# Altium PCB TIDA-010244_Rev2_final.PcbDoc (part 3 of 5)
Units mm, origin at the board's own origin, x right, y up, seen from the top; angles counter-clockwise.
Board outline 155.23 x 187.6 mm, 4 copper layers (GND/Signal 1, Solid GND Layer 1, Solid Power Layer 1, GND/Signal Layer 2), stack 1.59 mm thick; 350 components, 237 nets, 1153 pads, 380 vias.
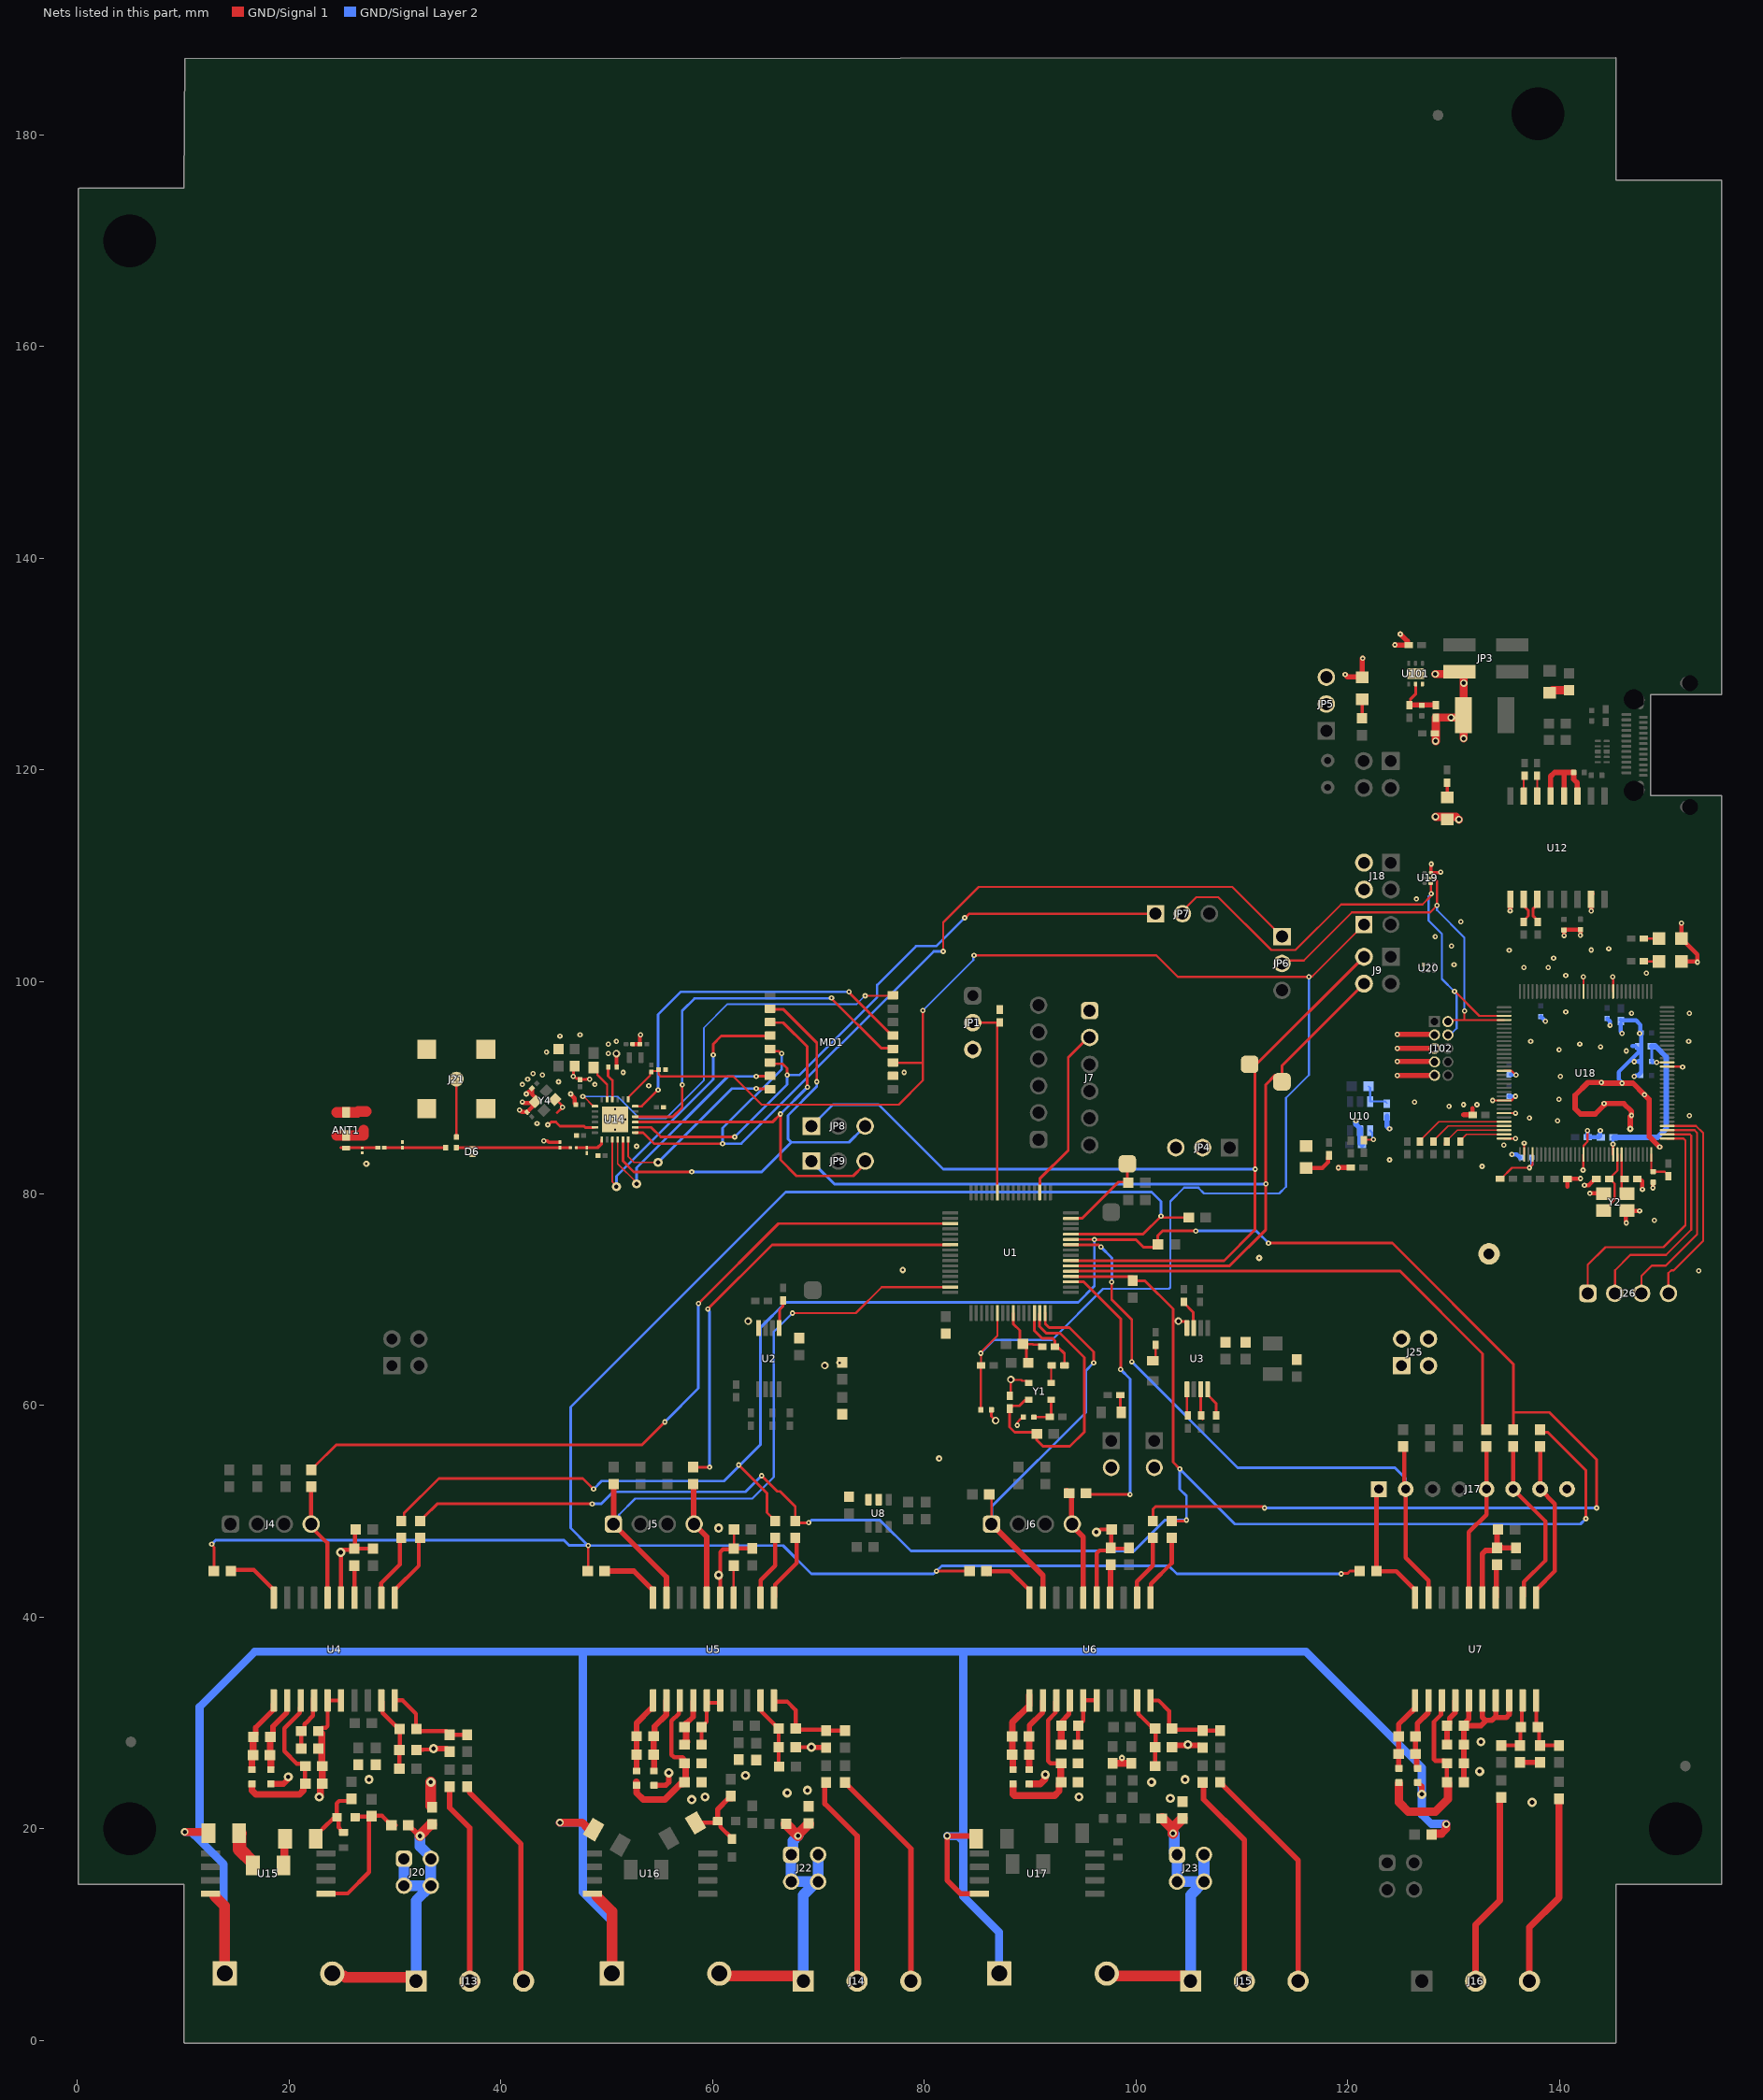
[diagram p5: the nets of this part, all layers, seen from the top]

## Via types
v1: diameter 0.5, hole 0.2, GND/Signal 1 to GND/Signal Layer 2, tented both sides, 236 vias
v2: diameter 0.5, hole 0.2, GND/Signal 1 to GND/Signal Layer 2, 46 vias
v3: diameter 0.864, hole 0.406, GND/Signal 1 to GND/Signal Layer 2, 41 vias
v4: diameter 0.7, hole 0.4, GND/Signal 1 to GND/Signal Layer 2, tented both sides, 40 vias
v5: diameter 0.61, hole 0.203, GND/Signal 1 to GND/Signal Layer 2, tented both sides, 10 vias
v6: diameter 0.4, hole 0.2, GND/Signal 1 to GND/Signal Layer 2, tented both sides, 7 vias

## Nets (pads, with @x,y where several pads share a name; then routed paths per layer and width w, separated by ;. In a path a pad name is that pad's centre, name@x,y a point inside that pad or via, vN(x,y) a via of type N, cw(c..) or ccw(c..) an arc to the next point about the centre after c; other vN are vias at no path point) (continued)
ADC_CS2: J5.1 R39.1 U1.31 U5.19 | length 62.1
  GND/Signal 1 w0.2: v1(67.564,68.707) 73.533,68.707 75.983,71.157 U1.31@82.466,71.157
  GND/Signal 1 w0.508: J5.1@50.648,48.768 50.66,48.781 50.66,52.565 R39.1@50.673,52.578 ; J5.1@50.927,48.768 50.927,48.489 55.651,43.764 U5.19@55.651,41.807
  GND/Signal Layer 2 w0.2: J5.1@50.648,48.768 51.18,49.3 51.18,49.656 52.705,51.181 63.754,51.181 65.786,53.213 65.786,66.929 v1(67.564,68.707)
ADC_CS3: J6.1 R42.1 U1.47 U6.19 | length 38.7
  GND/Signal 1 w0.254: R42.1@86.144,51.562 86.36,51.346 86.36,49.022 J6.1@86.233,48.895 ; U1.47@91.416,68.707 91.439,68.684 91.439,67.692 91.798,67.333 93.703,67.333 96.012,65.024 v1(96.012,64.008)
  GND/Signal 1 w0.508: J6.1@86.36,48.768 91.211,43.917 U6.19@91.211,41.807
  GND/Signal Layer 2 w0.254: J6.1@86.36,48.768 86.401,48.809 86.401,50.46 95.25,59.309 95.25,63.246 v1(96.012,64.008)
ADC_CS4: J17.2 R99.1 U1.58 U7.19 | length 62.4
  GND/Signal 1 w0.254: U1.58@93.266,75.157 U1.58@93.866,75.157 96.475,75.157 v1@96.73,74.902 ; v1(97.706,71.633) 97.706,69.987 99.605,68.089 v1@99.605,64.127
  GND/Signal 1 w0.381: R99.1@125.349,56.134 125.349,52.197 J17.2@125.476,52.07 125.476,45.593 127.635,43.434 U7.19@127.635,41.807
  GND/Signal Layer 2 w0.254: v1(96.687,74.945) 97.728,73.904 v1@97.728,71.613 ; v1@99.599,64.104 109.601,54.102 124.46,54.102 125.476,53.086 J17.2@125.476,52.07
  other v1: 99.595,64.101
ADC_DIN_MSP_DOUT: R29.2 R31.1 R37.2 R45.2 R90.2 U1.60 | length 210.2
  GND/Signal 1 w0.254: v1(12.7,46.863) 12.7,46.796 12.916,46.58 R29.2@12.916,44.323 ; R37.2@48.222,44.323 48.26,44.361 v1(48.26,46.736) ; v1(81.153,44.323) R45.2@84.29,44.323 ; U1.60@93.866,76.157 100.668,76.157 v1(102.362,77.851) 102.429,77.851 102.556,77.724 R31.1@104.991,77.724 ; v1(119.38,44.069) 119.427,44.116 120.002,44.116 120.209,44.323 R90.2@121.12,44.323
  GND/Signal Layer 2 w0.254: v1(12.7,46.863) 13.081,47.244 45.974,47.244 46.448,46.77 v1@48.226,46.77 ; v1(48.26,46.736) v1@48.226,46.77 ; v1@48.387,46.736 66.675,46.736 69.342,44.069 80.881,44.069 81.135,44.323 v1(81.153,44.323) 81.661,44.831 103.091,44.831 103.853,44.069 v1(119.38,44.069) ; v1(102.362,77.851) 102.362,79.248 101.473,80.137 66.929,80.137 46.609,59.817 46.609,48.387 v1@48.226,46.77
ADC_DIN_MSP_DOUT_H: J17.1 R90.1 U7.20 | length 12.9
  GND/Signal 1 w0.406: J17.1@122.682,52.07 122.72,52.032 R90.1@122.72,44.323 124.599,44.323 126.365,42.557 U7.20@126.365,41.807
ADC_DOUT_MSP_DIN: R25.1 R30.2 R38.2 R46.2 R91.2 U1.59 | length 205.4
  GND/Signal 1 w0.254: R30.2@30.607,49.06 30.869,49.322 30.869,49.792 34.163,53.086 47.752,53.086 v1(48.768,52.07) ; v1(62.484,54.356) 65.151,51.689 65.151,49.847 65.913,49.085 R38.2@65.913,49.06 ; U1.59@93.866,75.657 93.875,75.648 96.07,75.648 v1(96.079,75.64) 100.001,75.64 100.711,74.93 101.727,74.93 R25.1@101.854,75.057 ; R46.2@101.6,49.06 101.854,49.314 101.719,49.314 101.6,49.433 101.6,50.165 101.854,50.419 111.947,50.419 112.074,50.292 v1(112.141,50.292) ; R25.1@102.07,75.184 102.07,76.035 102.489,76.454 v1(105.664,76.454) ; v1(112.522,75.311) 124.206,75.311 135.636,63.881 135.636,59.32 ; R91.2@135.636,57.696 135.636,59.32 ; v1(143.51,50.292) 143.51,54.864 139.054,59.32 135.636,59.32
  GND/Signal Layer 2 w0.254: v1(48.768,52.07) 49.53,52.832 61.087,52.832 62.547,54.292 64.516,56.261 64.516,67.31 66.929,69.723 68.834,69.723 94.539,69.723 96.079,71.262 v1(96.079,75.64) ; v1(105.664,76.454) 111.379,76.454 v1(112.522,75.311) ; v1(112.141,50.292) v1(143.51,50.292)
ADC_DOUT_MSP_DIN_H: J17.6 R91.1 U7.12 | length 16.3
  GND/Signal 1 w0.381: J17.6@135.636,52.07 138.684,49.022 138.684,45.339 136.634,43.289 136.634,41.916 U7.12@136.525,41.807 ; J17.6@135.636,52.197 R91.1@135.636,56.096
ADC_DRDY_1: R26.2 U1.19 | length 74.7
  GND/Signal 1 w0.254: R26.2@22.098,53.886 22.098,53.911 22.446,54.259 22.471,54.259 24.473,56.261 53.34,56.261 v1(55.499,58.42) ; v1(58.674,69.596) 66.235,77.157 U1.19@82.466,77.157
  GND/Signal Layer 2 w0.254: v1(55.499,58.42) 58.674,61.595 v1(58.674,69.596)
ADC_DRDY_1_H: J4.4 R26.1 U4.16 | length 11.5
  GND/Signal 1 w0.381: J4.4@22.098,48.768 22.098,51.976 22.192,52.07 R26.1@22.352,52.07 ; J4.4@22.606,48.514 22.386,48.294 22.386,48.226 23.622,46.99 U4.16@23.622,41.148
ADC_DRDY_2: R33.2 U1.23 | length 42.1
  GND/Signal 1 w0.254: R33.2@58.166,54.14 v1(59.728,54.14) v1@59.817,54.229 ; v1(59.563,69.088) 65.632,75.157 U1.23@82.466,75.157
  GND/Signal Layer 2 w0.254: v1@59.563,69.021 59.728,68.856 v1(59.728,54.14)
ADC_DRDY_2_H: J5.4 R33.1 U5.16 | length 11.3
  GND/Signal 1 w0.508: R33.1@58.166,52.578 58.217,52.527 58.217,48.819 J5.4@58.268,48.768 ; J5.4@58.293,48.743 59.461,47.574 U5.16@59.461,41.807
ADC_DRDY_3: R41.2 U1.51 | length 27.2
  GND/Signal 1 w0.254: U1.51@93.866,71.657 95.055,71.657 98.552,68.16 v1@98.552,63.396 ; R41.2@95.377,51.816 95.631,51.562 v1(99.441,51.562)
  GND/Signal Layer 2 w0.254: v1(98.552,63.373) 99.441,62.484 v1(99.441,51.562)
ADC_DRDY_3_H: J6.4 R41.1 U6.16 | length 10.4
  GND/Signal 1 w0.508: R41.1@93.453,51.924 R41.1@93.472,51.943 ; J6.4@93.599,48.895 93.916,49.212 R41.1@93.916,51.816 ; J6.4@93.899,48.687 95.021,47.565 U6.16@95.021,41.807
ADC_DRDY_4: R87.2 U1.53 | length 49.4
  GND/Signal 1 w0.254: U1.53@93.866,72.657 124.955,72.657 132.748,64.864 132.748,58.069 133.032,57.785 R87.2@133.096,57.785
ADC_DRDY_4_H: J17.5 R87.1 U7.16 | length 14.7
  GND/Signal 1 w0.406: U7.16@131.445,41.807 131.445,48.006 133.096,49.657 133.096,51.689 J17.5@132.969,51.816 ; R87.1@132.969,56.007 133.096,55.88 J17.5@133.096,52.07
ADC_from_Buf_1: R18.1 U3.3 | length 2.8
  GND/Signal 1 w0.254: R18.1@104.521,69.758 104.521,69.658 105.41,68.769 U3.3@105.41,67.289
ADC_from_Buf_2: R21.1 U3.5 | length 3
  GND/Signal 1 w0.254: U3.5@104.859,60.964 104.859,61.446 U3.5@104.816,61.489 104.816,59.106 R21.1@104.902,59.02
ADC_from_Buf_3: R22.1 U3.7 | length 2.9
  GND/Signal 1 w0.254: U3.7@106.116,61.489 106.116,58.857 R22.1@106.299,58.674
ADC_from_Buf_4: R20.1 U3.8 | length 2.8
  GND/Signal 1 w0.254: U3.8@106.766,61.489 106.766,60.964 107.569,60.161 R20.1@107.569,59.055
ADC_SYNC_RESET: R24.1 R27.2 R34.2 R43.2 R88.2 U1.52 | length 163.3
  GND/Signal 1 w0.254: R27.2@32.385,49.06 32.385,49.085 32.733,49.433 32.758,49.433 33.998,50.673 v1(48.641,50.673) ; v1(64.643,53.34) 66.127,51.856 66.381,51.856 67.818,50.419 R34.2@67.818,49.06 67.983,48.895 v1(69.088,48.895) ; U1.52@93.866,72.157 R24.1@99.695,72.157 ; R24.1@99.695,71.755 100.838,71.755 103.505,69.088 103.505,54.61 v1(104.14,53.975) ; R43.2@103.378,49.06 104.619,49.06 104.708,49.149 v1(104.775,49.149) ; R88.2@138.176,57.696 138.413,57.459 138.883,57.459 142.494,53.848 v1(142.494,49.276)
  GND/Signal Layer 2 w0.254: v1(48.641,50.673) 49.476,50.673 50.619,51.816 63.119,51.816 v1(64.643,53.34) ; v1(69.088,48.895) 69.106,48.895 69.36,49.149 75.819,49.149 78.74,46.228 99.822,46.228 102.743,49.149 v1(104.775,49.149) ; v1@104.902,49.149 v1(104.775,49.149) ; v1(142.494,49.276) 141.986,48.768 109.347,48.768 v1(104.14,53.975) 104.14,52.07 104.775,51.435 v1(104.775,49.149)
ADC_SYNC_RESET_H: J17.7 R88.1 U7.11 | length 14.5
  GND/Signal 1 w0.406: U7.11@137.795,42.557 139.573,44.335 139.573,50.673 J17.7@138.176,52.07 ; J17.7@138.176,52.451 R88.1@138.176,56.096
Antenna: C114.1 L4.1 U14.1 | length 3.1
  GND/Signal 1 w0.25: U14.1@49.55,84.92 U14.1@49.55,85.095
  GND/Signal 1 w0.297: L4.1@47.117,84.328 L4.1@47.138,84.328 C114.1@48.006,84.328 ; C114.1@48.023,84.328 49.149,84.328 49.526,84.705 49.526,84.92 U14.1@49.526,85.071
BSL_Invoke: JP1.2 R10.2 U1.11 | length 18.4
  GND/Signal 1 w0.254: JP1.2@84.455,96.139 86.811,96.139 R10.2@86.868,96.082 ; R10.2@86.893,96.082 86.893,80.13 U1.11@86.916,80.107
CC_RESET: C5.2 C116.2 J2.1 MD1.11 R3.1 R122.2 U1.38 U14.13 | length 159.3
  GND/Signal 1 w0.2: U14.13@52.05,88.895 52.05,89.07 54.119,91.139 R122.2@54.119,91.457 ; R122.2@54.229,91.491 54.305,91.567 C116.2@54.864,91.567 ; C116.2@54.915,91.694 54.915,91.262 55.118,91.059 61.976,91.059 64.643,88.392 77.597,88.392 79.883,90.678 79.883,92.329 ; MD1.11@76.962,92.329 79.883,92.329 ; v1(79.883,97.282) 79.883,92.329 ; v1(84.709,102.489) 101.917,102.489 103.95,100.457 v1(116.332,100.457) 116.389,100.514 116.643,100.514 J2.1@121.539,105.41 ; C5.2@85.471,59.563 85.352,59.682 85.352,63.727 R3.1@85.379,63.754 85.379,65.024 85.39,65.024 85.487,65.121 85.487,65.132 86.916,66.561 U1.38@86.916,68.707
  GND/Signal Layer 2 w0.2: v1(79.883,97.282) 84.652,102.051 84.652,102.432 v1(84.709,102.489) ; v1(85.344,64.897) 86.614,66.167 92.075,66.167 96.901,70.993 103.124,70.993 103.251,71.12 103.251,79.248 104.552,80.549 105.918,80.549 ; 105.918,80.518 106.426,80.01 113.538,80.01 114.173,80.645 114.173,89.027 116.332,91.186 v1(116.332,100.457) v1@116.332,100.584
CC_SWDCK: JP7.1 MD1.6 U14.8 | length 62
  GND/Signal 1 w0.24: U14.8@52.7,86.245 54.217,86.245 55.118,85.344 v1(62.103,85.344) ; MD1.6@65.405,92.456 65.609,92.252 66.624,92.252 67.056,91.82 v1(67.056,91.186) ; v1(83.82,106.045) 83.89,106.045 84.271,106.426 JP7.1@101.854,106.426
  GND/Signal Layer 2 w0.24: v1(62.103,85.344) 67.056,90.297 v1(67.056,91.186) 68.214,91.186 75.554,98.526 75.554,99.684 79.234,103.364 81.139,103.364 v1(83.82,106.045)
CC_SWDIO: JP6.1 MD1.5 U14.7 | length 87
  GND/Signal 1 w0.2: v1@81.661,102.87 81.788,102.997 81.788,105.6 85.154,108.966 109.093,108.966 JP6.1@113.792,104.267
  GND/Signal 1 w0.24: U14.7@52.7,85.745 52.705,85.74 53.452,85.74 54.483,84.709 v1(60.96,84.709) ; MD1.5@65.381,93.623 MD1.5@65.405,93.599 ; MD1.5@65.659,93.536 65.759,93.436 66.277,93.436 66.495,93.218 v1(66.548,93.218)
  GND/Signal Layer 2 w0.24: v1(66.548,93.218) 66.548,91.757 60.96,86.169 v1(60.96,84.709) 62.738,84.709 80.899,102.87 v1(81.788,102.87)
CTS_FTDI: J7.2 U1.3 | length 16.8
  GND/Signal 1 w0.254: U1.3@90.916,80.107 90.916,81.391 93.599,84.074 93.599,92.837 95.441,94.679 J7.2@95.821,94.679
DCDC_HGND_A: C18.1 C19.2 FB1.1 U4.2 | length 7
  GND/Signal 1 w0.508: C19.2@18.288,28.448 18.478,28.638 18.478,29.654 19.791,30.967 19.791,32.061 U4.2@19.837,32.107
  GND/Signal 1 w0.635: C19.2@18.232,28.448 18.232,26.972 C18.1@18.206,26.946 18.288,26.864 FB1.1@18.288,25.821
DCDC_HGND_B: C27.1 C28.2 FB3.1 U5.2 | length 7
  GND/Signal 1 w0.559: C27.1@54.431,26.978 54.431,28.777 54.547,28.893 54.547,29.655 55.631,30.739 55.631,32.087 U5.2@55.651,32.107 ; FB3.1@54.503,25.754 C27.1@54.503,27.071
DCDC_HGND_C: C38.1 C39.2 FB5.1 U6.2 | length 6.7
  GND/Signal 1 w0.508: C39.2@89.938,28.727 89.938,29.74 91.165,30.967 91.165,32.061 U6.2@91.211,32.107
  GND/Signal 1 w0.635: C39.2@89.903,28.702 89.909,28.696 89.909,27.058 C38.1@89.916,27.051 ; C38.1@89.914,26.885 89.914,25.783 FB5.1@89.916,25.781
DCDC_HGND_D: C69.1 C70.2 FB7.1 U7.2 | length 7.1
  GND/Signal 1 w0.508: C69.1@126.403,27.178 C70.2@126.403,28.702 ; C69.1@126.492,27.178 126.523,27.147 126.523,25.765 126.594,25.694 FB7.1@126.619,25.694 ; C70.2@126.586,28.702 126.586,29.939 127.589,30.942 127.589,32.212 U7.2@127.635,32.258
DCDC_OUT_A: C18.2 C19.1 FB2.1 U4.1 | length 6.7
  GND/Signal 1 w0.508: C19.1@16.632,28.663 16.846,28.876 16.846,29.546 18.521,31.221 18.521,31.729 U4.1@18.542,31.75
  GND/Signal 1 w0.635: FB2.1@16.51,25.821 16.51,26.85 C18.2@16.606,26.946 ; C18.2@16.619,27.033 16.619,28.65 C19.1@16.632,28.663
DCDC_OUT_B: C27.2 C28.1 FB4.1 U5.1 | length 7.5
  GND/Signal 1 w0.559: FB4.1@52.832,25.44 52.832,26.924 C27.2@52.959,27.051 ; C27.2@52.832,26.978 52.832,29.972 54.196,31.336 54.361,31.336 54.381,31.357 U5.1@54.381,32.107
DCDC_OUT_C: C38.2 C39.1 FB6.1 U6.1 | length 7.6
  GND/Signal 1 w0.635: C38.2@88.314,27.051 88.314,28.605 88.314,30.021 89.916,31.623 U6.1@89.916,32.639 ; C38.2@88.392,27.051 88.361,27.02 88.361,25.752 88.369,25.745 FB6.1@88.394,25.745
DCDC_OUT_D: C69.2 C70.1 FB8.1 U7.1 | length 6.8
  GND/Signal 1 w0.508: C70.1@124.803,28.702 124.803,25.946 FB8.1@124.841,25.908 ; C70.1@124.803,28.791 124.803,29.845 126.365,31.369 U7.1@126.365,32.107
DEBUG_ID4: R113.1 U18.63 | length 4.5
  GND/Signal 1 w0.16: R113.1@130.556,84.963 130.604,84.963 131.226,85.584 U18.63@134.769,85.584
DEBUG_ID5: R114.1 U18.62 | length 6.3
  GND/Signal 1 w0.16: R114.1@129.159,84.582 129.159,84.788 130.356,85.984 U18.62@134.769,85.984
DEBUG_ID6: R115.1 U18.61 | length 7.3
  GND/Signal 1 w0.16: R115.1@128.016,84.963 128.064,84.963 129.486,86.384 U18.61@134.769,86.384
DEBUG_ID7: R116.1 U18.60 | length 8.6
  GND/Signal 1 w0.16: R116.1@126.873,85.09 126.921,85.09 128.616,86.784 U18.60@134.769,86.784
DIO6_SCL: MD1.16 U14.19 | length 39.4
  GND/Signal 1 w0.16: v1(47.752,89.154) 47.817,89.089 47.931,89.089 48.68,88.34 48.68,88.29 48.725,88.245 U14.19@48.9,88.245 ; v1(74.422,98.679) MD1.16@77.089,98.679
  GND/Signal Layer 2 w0.16: v1(47.752,89.154) 51.054,89.154 53.086,87.122 55.626,87.122 59.182,90.678 59.182,95.631 61.435,97.884 73.627,97.884 v1(74.422,98.679)
DIO8_SDA: MD1.4 U14.3 | length 27.5
  GND/Signal 1 w0.16: U14.3@50.55,85.095 50.55,81.086 50.927,80.709 v3(50.927,80.645)
  GND/Signal 1 w0.25: v1(60.071,93.091) 60.071,94.107 60.833,94.869 MD1.4@65.405,94.869
  GND/Signal Layer 2 w0.25: v3(50.927,80.645) 50.927,81.639 53.622,84.334 60.071,90.783 v1(60.071,93.091)
DIO11: MD1.7 U14.4 | length 22.8
  GND/Signal 1 w0.16: U14.4@51.05,85.095 51.05,82.808 52.832,81.026 v3(52.832,80.899)
  GND/Signal 1 w0.25: v1(64.135,91.059) 64.16,91.084 65.43,91.084 MD1.7@65.532,91.186
  GND/Signal Layer 2 w0.25: v3(52.832,80.899) 52.832,82.423 61.468,91.059 v1(64.135,91.059)
DIO13_PICO: MD1.8 U14.6 | length 18.2
  GND/Signal 1 w0.16: U14.6@52.05,85.095 52.05,83.459 52.578,82.931 v3(54.864,82.931)
  GND/Signal 1 w0.25: v1(64.135,89.916) 64.174,89.877 65.317,89.877 MD1.8@65.405,89.789
  GND/Signal Layer 2 w0.25: v3(54.864,82.931) 61.849,89.916 v1(64.135,89.916)
DIO21_POCI: MD1.12 U14.10 | length 36.5
  GND/Signal 1 w0.24: U14.10@52.7,87.245 56.257,87.245 ; 56.258,87.246 57.15,88.138 v1(57.15,90.273) ; v1(71.247,98.468) 71.247,98.425 75.946,93.726 MD1.12@77.089,93.726
  GND/Signal Layer 2 w0.24: v1(57.15,90.273) 57.15,97.282 58.293,98.425 71.204,98.425 v1(71.247,98.468) ; v1@71.247,98.425 v1@71.374,98.425
DIO24_SCLK: MD1.13 U14.12 | length 34.6
  GND/Signal 1 w0.24: U14.12@52.7,88.245 53.32,88.245 v1(54.864,89.789) ; v1(72.898,99.06) 72.948,99.01 72.948,98.917 76.869,94.996 MD1.13@76.962,94.996
  GND/Signal Layer 2 w0.24: v1(54.864,89.789) 54.864,96.901 57.023,99.06 v1(72.898,99.06)
GND: ANT1.2 ANT1.3 C1.2 C2.1 C3.1 C4.1 C5.1 C6.1 C7.2 C8.2 C9.2 C10.2 C11.1 C12.1 C13.1 C14.1 C15.2 C17.2 C24.2 C25.1 C26.2 C33.1 C34.2 C35.2 C36.1 C37.2 C45.1 C46.1 C47.1 C48.2 C68.2 C78.2 C79.1 C80.2 C81.2 C87.1 C88.2 C89.1 C90.1 C91.1 C92.1 C93.1 C94.2 C95.1 C96.2 C97.2 C98.1 C99.1 C100.2 C102.1 C103.2 C104.1 C105.1 C106.1 C107.1 C108.1 C110.1 C111.1 C112.2 C114.2 C115.2 C116.1 C118.2 C119.2 C120.1 C121.2 C122.2 C123.2 D6.1 J1.2 J3.2 J7.1 J17.8 J21.2 J21.3 J21.4 J21.5 J25.1 J25.2 J25.3 J25.4 J102.3 J102.5 J102.7 J102.9 JP1.3 JP3.4 JP4.2 JP4.3 JP5.2 JP5.3 LED0.1 LED1.1 LED2.2 LED3.2 LED6.1 MD1.10 R10.1 R112.1 R124.1 R126.1 TP1.1 U1.41 U2.4 U3.4 U4.15 U5.15 U6.15 U7.15 U8.2 U8.3 U10.2 U12.9 U12.15 U14.23 U14.25 U18.10 U18.17 U18.48 U18.55 U18.58 U18.64 U18.66 U18.80 U18.114 U19.3 U20.3 U101.3 U101.7@126.409,129.108 Y1.2 Y2.2 Y2.4 Y4.2 Y4.4 | length 196.7
  GND/Signal 1 w0.2: C10.2@88.076,60.872 88.179,60.975 88.179,62.382 v4@88.148,62.413 ; v4@88.212,62.432 88.249,62.395 89.162,62.395 89.251,62.306 89.681,62.306 Y1.2@89.881,62.106 ; v1@88.807,58.111 88.807,58.391 89.131,58.716 89.206,58.716 89.289,58.799 C11.1@89.289,58.874 ; C1.2@89.283,65.758 89.347,65.758 90.27,65.758 90.301,65.727 90.952,65.727 C12.1@91.152,65.527 ; v1(133.693,88.784) U18.55@134.769,88.784 135.464,88.784 135.719,89.039 135.719,89.046 135.855,89.182 v1(135.86,89.182) ; U18.64@134.769,85.184 135.73,85.184 v1@135.763,85.217 ; U18.58@134.769,87.584 v1(135.845,87.584) ; U18.48@134.769,91.584 135.479,91.584 135.843,91.22 v1@135.924,91.22 ; U18.66@136.669,83.684 v1(136.669,84.76) ; v1(142.23,82.209) 142.239,82.218 142.239,83.654 U18.80@142.269,83.684 142.269,84.511 142.659,84.901 v1(142.659,85.928) ; v2(142.24,100.457) 142.269,100.428 U18.17@142.269,99.084 ; U18.10@145.069,99.084 145.069,100.16 ; U18.114@150.169,91.984 151.359,91.984
  GND/Signal 1 w0.25: v2(44.45,86.487) 44.518,86.487 44.772,86.741 45.212,86.741 45.593,86.36 47.879,86.36 48.006,86.233 U14.23@48.768,86.233 ; Y4.2@45.115,88.879 45.233,88.879 45.72,88.392 45.719,88.391 45.719,88.01 45.339,87.63 ; C112.2@46.99,91.821 46.863,91.694 v1(46.863,91.059) 46.931,91.059 47.131,90.859 47.444,90.859 C106.1@47.498,90.805 ; C106.1@47.498,90.754 47.524,90.78 48.108,90.78 48.133,90.805 ; U14.23@48.768,86.245 U14.23@48.9,86.245
  GND/Signal 1 w0.254: C33.1@62.04,48.26 62.04,46.291 C24.2@62.103,46.228 ; C5.1@86.352,59.563 86.352,58.932 86.614,58.67 v4@86.614,58.547 ; U1.41@88.416,68.707 88.416,67.667 89.027,67.056 89.027,65.659 C1.2@89.205,65.837 ; C1.2@89.347,65.758 89.662,65.443 C3.1@89.662,64.117 ; C3.1@89.713,63.919 C3.1@89.827,63.919 ; v4(104.013,67.945) 104.054,67.904 104.718,67.904 104.816,67.806 U3.4@104.816,67.289
  GND/Signal 1 w0.3: 44.323,84.963 44.407,84.963 44.533,84.836 C115.2@45.593,84.836 ; U101.7@126.409,129.108 U101.7@126.676,129.108 ; U19.3@127.864,110.302 127.853,110.302 127.853,111.089 v1(127.889,111.125) ; U19.3@127.875,110.302 128.663,110.302 128.724,110.363 v1(128.778,110.363)
  GND/Signal 1 w0.305: C13.1@108.543,65.855 C13.1@108.55,65.863
  GND/Signal 1 w0.381: U4.15@24.912,41.812 24.912,46.121 25.135,46.344 25.897,46.344 C17.2@25.908,46.355 ; C17.2@25.949,46.711 C17.2@26.162,46.711 ; C17.2@26.162,46.609 26.232,46.679 26.232,48.19 C26.2@26.302,48.26 ; C17.2@26.25,46.521 C17.2@26.349,46.62 ; C17.2@26.441,46.479 26.467,46.453 C25.1@27.94,46.453 ; v2(41.783,87.884) 41.815,87.884 42,87.699 C4.1@42.463,87.699 ; v2(42.037,88.646) 42.069,88.646 42.164,88.552 42.893,88.552 Y4.4@42.926,88.519 ; C4.1@42.481,87.694 Y4.4@43.277,88.489 ; v1@42.545,89.408 42.545,89.507 C81.2@42.933,89.895 ; C81.2@42.947,89.937 42.947,89.909 C81.2@42.933,89.895 ; Y4.4@43.281,88.672 43.312,88.702 43.312,89.034 42.958,89.388 42.958,89.869 C81.2@42.933,89.895 ; v4(50.927,93.218) 50.936,93.209 50.936,91.957 C104.1@50.946,91.948 ; C102.1@52.451,94.107 C103.2@53.086,94.107 ; C103.2@53.137,94.107 53.137,94.888 53.213,94.964 v2(53.213,94.996) ; U5.15@60.731,41.807 60.731,46.126 60.98,46.375 C24.2@62.027,46.375 ; C24.2@62.053,46.482 C34.2@63.754,46.482 ; v3(96.266,48.006) 96.397,48.006 96.651,48.26 C36.1@97.663,48.26 ; U6.15@96.291,41.807 96.291,45.999 96.566,46.274 97.328,46.274 C35.2@97.409,46.355 ; C35.2@97.657,46.488 C36.1@97.657,48.139 ; C35.2@97.663,46.355 C35.2@97.682,46.374 ; C35.2@97.752,46.444 C37.2@99.339,46.444
  GND/Signal 1 w0.4: v2(46.609,89.408) 46.609,89.381 46.99,89 46.99,88.519 47.062,88.447 47.062,88.402 47.072,88.392 C111.1@47.092,88.392 C111.1@47.117,88.392 ; R126.1@131.789,87.569 131.789,88.073 ; v1(135.343,106.701) U12.9@135.343,107.205 ; C46.1@140.421,104.884 140.44,104.903 C45.1@141.845,104.903 ; v1(140.439,104.36) C46.1@140.439,104.864 ; 140.748,80.657 R124.1@140.748,81.161 ; R124.1@140.979,81.415 140.987,81.407 v1(141.986,81.407) ; v1(141.972,104.386) C45.1@141.972,104.903 ; v1(142.367,80.772) 142.386,80.791 142.795,80.791 143.293,81.289 C123.2@143.293,81.405 ; v1(142.875,80.01) 143.623,80.01 Y2.4@143.64,80.026 ; v1(143.002,106.68) 142.989,106.693 142.989,108.178 142.983,108.185 U12.15@143.129,108.331 ; Y2.2@146.273,77.952 146.285,77.94 146.285,77.235 v1(146.304,77.216) ; Y2.2@146.832,78.362 146.835,78.359 v1(147.574,78.359) ; C122.2@147.614,81.355 147.809,81.16 147.809,80.41 v1(147.828,80.391) ; v1(148.825,80.533) C87.1@148.825,81.037 ; v1(151.511,105.537) 151.521,105.527 LED3.2@151.521,104.553 ; LED2.2@151.682,101.767 LED2.2@151.52,101.93 152.932,101.93 153.008,101.854 v1(153.035,101.854) ; LED3.2@151.892,103.689 151.92,103.689 153.016,102.593 v1@153.016,101.873
  GND/Signal 1 w0.5: v1(119.126,82.423) 119.158,82.455 C7.2@120.279,82.455 ; v1(119.761,129.032) 120.002,128.791 LED6.1@121.339,128.791 ; LED6.1@121.372,128.791 121.372,130.516 v1(121.412,130.556) ; v1(124.46,131.826) 124.479,131.807 125.643,131.807 125.659,131.823 125.625,131.857 125.625,132.185 v1(124.968,132.842) ; v1(124.68,93.717) 128.108,93.717 J102.5@128.124,93.733 ; v1(124.686,92.483) 128.093,92.483 J102.7@128.2,92.376 ; v1(124.686,95.025) 128.054,95.025 J102.3@128.091,95.062 ; v1(124.691,91.148) 124.702,91.159 J102.9@128.128,91.159 ; 130.971,87.442 R126.1@131.832,87.442 ; 142.113,87.503 141.986,87.503 141.478,88.011 141.478,89.281 142.686,90.489 v1(143.958,90.489) 144.023,90.424 146.94,90.424 v1(148.039,89.325) ; 142.152,87.503 143.383,87.503 v1@144.272,88.392 ; v1(144.216,88.489) 146.08,88.489 146.812,87.757 v1(146.812,87.376) 146.685,87.249 v5(146.685,86.106) ; v1@148.082,89.281 148.479,88.884 148.479,85.374 v1(149.469,84.384)
  GND/Signal 1 w0.508: U7.15@132.715,41.807 132.715,45.974 133.015,46.274 C68.2@133.904,46.274 ; C68.2@134.112,46.736 134.112,48.387 C120.1@134.239,48.514 ; C68.2@134.366,46.736 134.582,46.52 C121.2@135.89,46.52
  GND/Signal 1 w0.762: v4(128.267,129.069) 130.354,129.069 JP3.4@130.57,129.285 130.944,128.912 C47.1@130.944,125.171 ; v4(128.288,115.587) 130.229,115.587 130.493,115.323 v4(130.503,115.333) ; v4@128.321,122.72 R112.1@128.321,124.952 130.725,124.952 C47.1@130.944,125.171 ; v4(130.951,122.987) 130.951,125.164 C47.1@130.944,125.171
  GND/Signal 1 w1: 24.511,85.471 27.051,85.471 27.051,85.979 ; 24.511,87.671 26.457,87.671 26.543,87.757 27.305,87.757
  GND/Signal Layer 2 w0.2: v1(88.798,58.111) 88.805,58.104 v1@88.811,58.104
  GND/Signal Layer 2 w0.4: v1@49.911,86.995 v1(50.8,86.995) ; v1@50.8,86.106 v1(50.8,86.995) ; v1@50.8,87.884 v1(50.8,86.995) ; v1(51.775,86.995) v1(50.8,86.995) ; C91.1@135.262,89.205 135.285,89.182 v1(135.86,89.182) ; C92.1@135.42,91.22 v1@135.924,91.22 ; v1(135.509,83.693) 135.528,83.674 135.966,83.674 C99.1@136.24,83.4 ; C93.1@138.255,96.695 v1(138.684,96.266) ; C88.2@142.659,85.424 v1(142.659,85.928) ; C88.2@142.666,85.313 143.749,85.313 143.86,85.424 v1(143.86,85.928) ; C95.1@144.526,96.52 144.526,96.503 144.762,96.266 144.762,96.008 v1@144.782,95.989 ; C94.2@145.79,95.996 145.79,95.283 145.923,95.15 v1(145.923,95.123) ; C94.2@145.796,96.393 145.847,96.342 147.244,96.342 147.657,95.929 147.657,95.229 C90.1@147.707,95.179 147.707,91.44 ; v1(145.923,90.424) 145.923,90.451 145.589,90.785 145.589,91.474 147.572,93.457 147.657,93.457 ; 146.868,93.946 147.131,93.946 C97.2@147.438,93.64 ; v1@147.153,92.46 C98.1@147.657,92.46 ; v1@147.178,91.135 147.402,91.135 147.682,91.415 ; v1(147.574,95.123) 147.605,95.154 C90.1@147.682,95.154
  GND/Signal Layer 2 w0.5: v1(120.777,86.868) 120.777,86.528 121.169,86.136 121.169,84.769 C6.1@121.342,84.595 ; C8.2@123.698,87.284 123.698,87.134 123.698,86.36 v1(123.952,86.106)
  other v1: 153.166,72.692 148.971,77.47 132.695,82.558 123.952,83.185 134.747,84.582 135.845,85.184 50.8,86.02 139.827,86.868 49.825,86.995 152.278,87.361 50.8,87.97 129.566,88.238 130.937,88.392 132.207,88.392 126.325,88.638 139.954,88.9 42.418,89.408 140.081,91.059 147.066,91.059 135.89,91.186 78.105,91.44 151.638,91.948 147.066,92.456 146.304,93.472 139.969,93.579 143.891,93.853 141.919,94.119 152.207,94.372 137.291,94.379 144.78,95.885 152.273,97.028 140.589,97.155 140.589,100.584 148.212,100.812 136.652,101.346 139.446,102.235 135.258,102.971 143.002,102.997 129.794,103.378 128.27,104.267 126.492,107.823
  other v2: 52.832,84.455 44.069,84.963 43.434,86.614 137.16,87.122 45.847,88.138 53.975,90.17 42.037,90.297 48.895,90.297 45.466,90.551 42.545,90.805 48.387,90.805 43.942,91.186 43.053,91.313 51.562,91.44 50.165,93.218 44.323,93.345 50.165,94.107 50.927,94.361 45.593,94.869 47.498,94.996 146.812,97.028 145.034,100.457 138.938,101.346 130.048,101.6 144.653,103.124 130.683,105.664
  other v3: 60.579,43.942 24.892,46.101 60.579,48.387
  other v4: 86.741,58.547 88.179,62.419 70.612,63.754 63.373,67.945 128.302,122.749 129.766,124.951 130.967,128.216
  other v5: 81.408,54.954 72.009,64.008 77.978,72.771 111.633,73.914 27.305,82.804
HFXIN: C12.2 R11.2 U1.45 | length 6.8
  GND/Signal 1 w0.254: U1.45@90.416,68.707 90.416,67.031 91.115,66.332 92.108,66.332 92.352,66.087 C12.2@92.352,65.527 ; C12.2@92.412,65.512 C12.2@92.595,65.512 ; C12.2@92.621,65.503 93.251,64.874 R11.2@93.251,63.76
HFXOUT: C10.1 R9.1 U1.46 Y1.3 | length 26.1
  GND/Signal 1 w0.254: C10.1@88.054,59.698 88.054,57.927 88.541,57.44 90.479,57.44 R9.1@90.637,57.283 ; C10.1@88.271,59.838 88.37,59.938 88.977,59.938 89.507,60.468 Y1.3@89.869,60.468 ; R9.1@90.61,57.283 90.61,56.716 91.213,56.113 93.767,56.113 95.123,57.469 95.123,64.516 92.84,66.799 91.52,66.799 90.904,67.416 U1.46@90.904,68.658
HGND_A: J10.2 J13.1 J20.1 J20.2 J20.3 J20.4 R100.1 R104.2 | length 31.3
  GND/Signal 1 w0.5: R100.1@31.28,20.32 31.305,20.32 32.175,19.45 32.315,19.45 v3@32.385,19.38
  GND/Signal 1 w1.016: J10.2@24.084,6.304 24.33,6.058 25.232,6.058 25.321,5.969 31.623,5.969 J13.1@32.004,5.588 ; v3(32.385,19.304) 32.385,19.38 33.369,20.365 R104.2@33.483,20.365
  GND/Signal Layer 2 w1.016: J10.2@24.084,6.304 J10.2@24.33,6.55 ; J20.1@30.861,17.018 J20.2@30.861,14.605 J20.4@33.401,14.605 ; J13.1@32.004,5.588 32.004,13.208 J20.4@33.401,14.605 ; v3(32.385,19.304) 32.385,18.306 33.401,17.29 J20.4@33.401,14.605
HGND_A_FB: C20.2 C21.2 C22.2 C23.2 C50.2 C52.1 C59.2 C61.1 FB1.2 R104.1 U4.5 U4.6 | length 18
  GND/Signal 1 w0.3: C22.2@23.015,28.984 C22.2@23.015,29.415 ; R104.1@33.401,22.136 R104.1@33.528,22.009
  GND/Signal 1 w0.381: C22.2@23.015,29.415 23.121,29.521 23.472,29.521 23.647,29.696 U4.5@23.647,32.107 ; U4.5@23.797,32.107 U4.6@24.917,32.107 ; C61.1@32.004,27.432 C61.1@32.024,27.452 ; C61.1@32.405,27.452 32.655,27.452 32.67,27.467 33.563,27.467 v3(33.655,27.559)
  GND/Signal 1 w0.5: v3(33.655,27.559) 34.887,27.559 34.929,27.517 34.954,27.517 35.179,27.292 C59.2@35.179,27.267
  GND/Signal 1 w0.559: FB1.2@18.288,24.217 19.471,24.217 19.881,24.627 19.881,24.834 v3(19.939,24.892)
  GND/Signal 1 w0.635: v3(22.86,22.987) 22.86,23.049 22.969,23.158 22.969,24.099 23.127,24.257 C20.2@23.152,24.257 ; C22.2@23.097,28.997 23.097,27.862 23.1,27.858 C21.2@23.1,26.21 ; C20.2@23.138,24.293 23.145,24.3 23.145,25.901 C21.2@23.155,25.911
  GND/Signal 1 w1.016: R104.1@33.401,22.136 v3(33.401,24.384)
  other v3: 27.559,24.638
HGND_B: J11.2 J14.1 J22.1 J22.2 J22.3 J22.4 R101.1 R102.2 | length 30.8
  GND/Signal 1 w1.016: J11.2@60.833,6.096 68.072,6.096 J14.1@68.58,5.588 ; R101.1@66.929,20.447 v4(68.072,19.304) 68.072,19.431 R102.2@69.088,20.447
  GND/Signal Layer 2 w1.016: v4(68.072,19.304) 67.589,18.821 67.589,17.678 J22.1@67.437,17.526 J22.2@67.437,14.986 J22.4@69.85,14.986 ; J14.1@68.58,5.588 68.58,13.716 J22.4@69.85,14.986 ; J22.3@69.977,17.653 J22.3@69.977,17.526 J22.4@69.977,14.986 J22.4@69.85,14.986
HGND_B_FB: C29.2 C30.2 C31.2 C32.2 C53.2 C55.1 C62.2 C64.1 FB3.2 R102.1 U5.5 U5.6 | length 10.2
  GND/Signal 1 w0.381: C32.2@58.966,27.94 C31.2@58.966,29.591 58.991,29.591 59.275,29.876 59.275,29.901 59.461,30.086 59.461,31.852 U5.5@59.436,31.877 ; U5.5@59.571,31.877 U5.6@60.579,31.877 ; C64.1@67.856,27.686 v3(69.342,27.686)
  GND/Signal 1 w0.5: FB3.2@54.483,24.09 55.586,24.09 55.879,24.383 55.879,25.145 v3@55.88,25.146 ; v3(69.342,27.686) 69.361,27.667 70.593,27.667 C62.2@70.612,27.648
  other v3: 58.039,22.733 59.309,22.987 67.056,23.368 68.961,23.622 63.119,25.019 55.88,25.273
HGND_C: J12.2 J15.1 J23.1 J23.2 J23.3 J23.4 R103.1 R105.2 | length 31.5
  GND/Signal 1 w0.5: J12.2@96.918,6.622 J12.2@97.236,6.304 ; J12.2@97.155,6.223 J12.2@97.536,5.842
  GND/Signal 1 w1.016: J12.2@97.791,6.096 104.648,6.096 J15.1@105.156,5.588 ; R103.1@102.489,20.955 103.505,19.939 ; v4(103.505,19.558) 103.505,19.939 ; R105.2@104.394,20.955 103.505,20.066 103.505,19.939
  GND/Signal Layer 2 w1.016: v4(103.505,19.558) 103.619,19.444 103.619,17.793 J23.1@103.886,17.526 J23.2@103.886,14.986 J23.4@106.426,14.986 ; J15.1@105.156,5.588 105.156,13.716 J23.4@106.426,14.986 ; J23.3@106.426,17.526 J23.4@106.426,14.986
HGND_C_FB: C40.2 C41.2 C42.2 C43.2 C56.2 C58.1 C65.2 C67.1 FB5.2 R105.1 U6.5 U6.6 | length 12
  GND/Signal 1 w0.4: C43.2@94.526,27.94 94.541,27.955 94.541,29.644 C42.2@94.615,29.718 ; C42.2@94.555,29.718 94.58,29.718 94.855,29.993 94.855,30.018 95.021,30.184 95.021,31.979 U6.5@94.996,32.004 ; U6.5@95.021,32.107 U6.6@96.191,32.107
  GND/Signal 1 w0.5: C67.1@103.505,27.75 103.625,27.87 104.832,27.87 v3(104.902,27.94) 104.972,27.87 105.95,27.87 C65.2@106.172,27.648
  GND/Signal 1 w0.635: FB5.2@89.916,24.217 90.964,24.217 91.398,24.651 91.398,25.051 v3(91.442,25.095) ; C56.2@97.948,26.162 C58.1@99.441,26.162
  other v3: 103.251,22.86 94.615,22.987 101.473,24.384 104.648,24.638
  other v5: 98.679,26.67
HGND_D_FB: C71.2 C72.2 C73.2 C74.2 C75.2 C77.1 FB7.2 J10.1 J11.1 J12.1 R58.2 R64.2 R70.2 R106.1 U7.5 U7.6 U7.7 U7.8 U15.4 U16.4 U17.4 | length 278.2
  GND/Signal 1 w0.5: U7.6@132.715,32.107 132.715,30.519 133.008,30.226 133.096,30.226 133.604,30.226 133.858,30.48 133.946,30.48 ; U7.7@133.985,31.369 133.985,30.519 133.946,30.48 ; U7.8@135.255,32.107 135.255,30.773 134.962,30.48 133.946,30.48
  GND/Signal 1 w0.508: R70.2@84.836,19.05 84.582,19.304 v4(82.169,19.304) 82.169,15.113 83.439,13.843 U17.4@85.217,13.843 ; FB7.2@126.619,24.344 126.644,24.344 127,23.988 v3(127,23.241) ; C71.2@131.064,24.384 130.975,24.473 C72.2@130.975,26.162 C74.2@130.975,27.94 C73.2@130.975,29.718 132.588,29.718 133.096,30.226 ; C73.2@131.064,29.972 131.445,30.353 U7.5@131.445,32.107 ; C75.2@136.271,26.251 138.011,26.251 C77.1@138.049,26.289
  GND/Signal 1 w0.762: v4(10.16,19.685) R58.2@12.319,19.685 ; v4(45.593,20.574) 47.691,20.574 48.229,20.036 48.484,20.036 R64.2@48.641,20.193 ; R106.1@127.927,19.431 128.021,19.525 128.851,19.525 129.297,19.971 v4(129.297,20.423)
  GND/Signal 1 w1.016: U15.4@12.976,13.635 13.924,12.687 J10.1@13.924,6.304 ; J10.1@13.716,6.35 J10.1@13.716,6.512 ; U16.4@49.044,13.635 50.5,12.179 J11.1@50.5,6.304
  GND/Signal Layer 2 w0.762: v4(10.16,19.685) 10.795,19.685 11.557,18.923 ; J10.1@13.843,6.35 13.843,16.637 11.557,18.923 ; v4(45.593,20.574) 47.752,20.574 ; J11.1@50.927,6.096 50.5,6.523 50.5,11.222 47.752,13.97 47.752,20.574 ; v4(82.169,19.304) 82.188,19.285 83.204,19.285 83.566,18.923 ; J12.1@87.076,6.304 87.076,10.206 83.693,13.589 83.693,36.703 ; v4@129.286,20.447 127.889,20.447 127,21.336 v3(127,23.241) 127,25.781 116.078,36.703 83.693,36.703 ; v4(129.297,20.423) v4@129.297,20.447 ; 11.557,18.923 11.557,31.496 16.764,36.703 47.752,36.703 ; 47.752,20.574 47.752,36.703 ; 47.752,36.703 83.693,36.703
  other v3: 137.414,22.479 132.461,25.4 132.588,28.194
HLDO_IN_A: C20.1 C21.1 FB2.2 U4.3 | length 15.8
  GND/Signal 1 w0.406: U4.3@21.082,31.496 21.011,31.425 21.011,30.917 19.558,29.464 19.558,27.305 20.741,26.122 21.338,26.122 C21.1@21.552,25.908 ; U4.3@21.107,31.496 U4.3@21.107,32.107 ; C20.1@21.497,24.605 C21.1@21.497,25.908
  GND/Signal 1 w0.635: FB2.2@16.51,24.217 16.51,23.613 16.882,23.241 20.998,23.241 21.369,23.613 21.369,24.099 21.527,24.257 C20.1@21.552,24.257
HLDO_IN_B: C29.1 C30.1 FB4.2 U5.3 | length 15.3
  GND/Signal 1 w0.406: U5.3@56.921,32.107 56.825,32.01 56.825,30.86 56.134,30.169 56.134,26.961 56.372,26.723 57.187,26.723 C30.1@57.459,26.451 ; C30.1@57.311,26.127 C30.1@57.311,26.192
  GND/Signal 1 w0.635: FB4.2@52.797,24.404 52.822,24.404 52.829,24.396 52.829,24.371 52.832,24.369 FB4.2@52.832,24.09 52.832,23.368 53.467,22.733 55.499,22.733 56.992,24.226 57.208,24.226 C29.1@57.366,24.384 ; C29.1@57.459,24.384 C30.1@57.459,26.107
HLDO_IN_C: C40.1 C41.1 FB6.2 U6.3 | length 15.8
  GND/Signal 1 w0.406: U6.3@92.481,32.107 92.385,32.01 92.385,30.917 91.694,30.226 91.694,26.4 91.932,26.162 C41.1@92.901,26.162
  GND/Signal 1 w0.635: FB6.2@88.392,24.217 88.392,23.241 88.521,23.112 92.327,23.112 92.743,23.528 92.743,24.226 92.901,24.384 C40.1@92.926,24.384 C40.1@93.091,24.384 ; C40.1@92.901,24.409 C41.1@92.901,26.162
HLDO_IN_D: C71.1 C72.1 FB8.2 U7.3 | length 17.6
  GND/Signal 1 w0.406: U7.3@128.905,32.107 128.808,32.01 128.808,30.773 128.143,30.108 128.143,26.527 128.265,26.405 129.078,26.405 C72.1@129.159,26.324 ; C71.1@129.375,24.473 C72.1@129.375,26.162
  GND/Signal 1 w0.8: FB8.2@124.841,24.257 124.841,22.479 125.73,21.59 128.27,21.59 129.475,22.795 129.475,24.309 129.4,24.384 C71.1@129.375,24.384
HLDO_OUT_A: C22.1 C23.1 U4.4 | length 5.4
  GND/Signal 1 w0.4: C23.1@21.082,27.559 21.171,27.648 C22.1@21.171,29.21 ; C22.1@21.336,29.083 21.471,29.218 21.471,29.873 21.57,29.972 21.59,29.972 22.277,30.659 22.277,32.31 U4.4@22.352,32.385
HLDO_OUT_B: C31.1 C32.1 U5.4 | length 4.2
  GND/Signal 1 w0.508: C31.1@57.513,29.799 C31.1@57.599,29.799 ; C31.1@57.599,29.926 57.612,29.939 57.612,30 58.166,30.554 U5.4@58.166,32.004
  GND/Signal 1 w0.635: C32.1@57.404,28.194 C32.1@57.572,28.194 ; C32.1@57.513,28.312 C31.1@57.513,29.926
HLDO_OUT_C: C42.1 C43.1 U6.4 | length 4.3
  GND/Signal 1 w0.457: C42.1@92.964,30.099 93.68,30.815 93.68,32.036 U6.4@93.751,32.107
  GND/Signal 1 w0.635: C42.1@92.941,29.703 92.941,27.963 C43.1@93.091,27.813 ; C42.1@92.955,29.718 C42.1@92.964,29.727
HLDO_OUT_D: C73.1 C74.1 U7.4 | length 4.2
  GND/Signal 1 w0.508: C73.1@129.375,29.718 129.375,27.978 C74.1@129.413,27.94 ; C73.1@129.621,29.939 129.621,30.434 130.129,30.942 130.129,32.061 U7.4@130.175,32.107
HY_RX: JP8.3 MD1.2 U14.5 | length 43.5
  GND/Signal 1 w0.16: U14.5@51.55,85.078 U14.5@51.562,85.09
  GND/Signal 1 w0.254: U14.5@51.55,85.078 51.55,83.07 52.578,82.042 v1(58.039,82.042) ; MD1.2@65.405,97.409 66.675,97.409 69.85,94.234 v1(69.85,90.551)
  GND/Signal Layer 2 w0.254: v1(58.039,82.042) 64.643,82.042 67.437,84.836 ; v1(69.85,90.551) 69.85,90.106 67.128,87.384 67.128,85.145 67.437,84.836 ; JP8.3@74.549,86.106 74.168,86.106 72.898,84.836 67.437,84.836
HY_TX: JP9.3 MD1.3 U14.9 | length 39
  GND/Signal 1 w0.254: U14.9@52.7,86.745 62.23,86.745 ; 62.23,86.741 65.659,86.741 v1(66.421,87.503) 66.421,83.185 67.945,81.661 73.301,81.661 74.19,82.55 JP9.3@74.295,82.55 ; MD1.3@65.532,96.139 66.675,96.139 68.961,93.853 v1(68.961,90.043)
  GND/Signal Layer 2 w0.254: v1(66.421,87.503) v1(68.961,90.043)
I_Neutral_N: C76.2 C77.2 R95.2 U7.10 | length 5.9
  GND/Signal 1 w0.35: U7.10@137.795,32.107 137.795,29.891 137.841,29.845 C76.2@137.922,29.845 ; C76.2@137.96,29.591 138.068,29.483 138.068,27.832 C77.2@138.049,27.813 ; C77.2@138.265,27.851 139.654,27.851 139.7,27.805 R95.2@139.7,27.559
I_Neutral_N_IN: J16.3 R94.1 | length 18.4
  GND/Signal 1 w0.635: J16.3@137.16,5.588 137.16,10.668 139.954,13.462 R94.1@139.954,22.822
I_Neutral_P: C75.1 C76.1 R93.2 U7.9 | length 5.8
  GND/Signal 1 w0.35: R93.2@134.62,27.813 134.658,27.851 C75.1@136.271,27.851 ; C75.1@136.315,27.896 136.315,29.546 C76.1@136.36,29.591 ; C76.1@136.442,29.674 136.442,32.024 U7.9@136.525,32.107
I_Neutral_P_IN: J16.2 R92.1 | length 18.3
  GND/Signal 1 w0.635: J16.2@132.08,5.588 132.08,10.922 134.366,13.208 R92.1@134.366,22.987
I_Phase_A_N: C59.1 C60.1 R75.2 U4.10 | length 8.9
  GND/Signal 1 w0.381: U4.10@29.992,32.112 30.734,32.112 32.004,30.842 32.004,29.691 C60.1@32.168,29.526 ; C60.1@32.048,29.406 32.245,29.21 34.861,29.21 35.115,28.956 C59.1@35.179,28.956 ; C59.1@35.179,28.867 R75.2@36.83,28.867
I_Phase_A_N_IN: J13.3 R74.1 | length 19.8
  GND/Signal 1 w0.508: R74.1@36.777,24.012 37.051,23.739 37.051,23.401 41.91,18.542 J13.3@41.91,6.35
I_Phase_A_P: C60.2 C61.2 R77.2 U4.9 | length 7.2
  GND/Signal 1 w0.381: U4.9@28.722,32.112 28.837,31.997 28.837,30.932 30.078,29.691 30.139,29.691 30.339,29.49 C60.2@30.339,29.43 ; R77.2@30.442,25.692 C61.2@30.442,27.432 30.48,27.47 C60.2@30.48,29.464
I_Phase_A_P_IN: J13.2 R76.1 | length 19.3
  GND/Signal 1 w0.508: R76.1@35.179,24.113 35.179,21.971 37.084,20.066 J13.2@37.084,5.588
I_Phase_B_N: C62.1 C63.1 R79.2 U5.10 | length 8.5
  GND/Signal 1 w0.381: U5.10@65.786,32.004 67.056,32.004 67.856,31.204 C63.1@67.856,29.464 67.964,29.356 70.593,29.356 C62.1@70.612,29.337 ; C62.1@70.739,29.248 R79.2@72.232,29.248 ; R79.2@72.517,29.248 R79.2@72.555,29.21
I_Phase_B_N_IN: J14.3 R78.1 | length 21.3
  GND/Signal 1 w0.508: R78.1@72.644,24.257 72.644,24.194 78.74,18.098 78.74,5.842 J14.3@78.994,5.588
I_Phase_B_P: C63.2 C64.2 R81.2 U5.9 | length 6.6
  GND/Signal 1 w0.381: U5.9@64.541,32.107 64.651,31.998 64.651,31.044 65.947,29.749 66.009,29.749 C63.2@66.04,29.718 ; C63.2@66.256,29.426 C64.2@66.256,27.686 66.256,25.946 R81.2@66.294,25.908
I_Phase_B_P_IN: J14.2 R80.1 | length 19.8
  GND/Signal 1 w0.508: R80.1@70.612,24.346 70.612,22.352 73.66,19.304 J14.2@73.66,5.842
I_Phase_C_N: C65.1 C66.1 R83.2 U6.10 | length 10
  GND/Signal 1 w0.381: U6.10@101.371,32.107 102.132,32.107 103.124,31.115 103.124,29.749 C66.1@103.282,29.591 ; C66.1@103.416,29.464 103.524,29.356 105.156,29.356 106.153,29.356 C65.1@106.172,29.337 ; C66.1@103.505,29.337 105.156,29.337 ; C65.1@106.172,29.265 R83.2@107.95,29.265
I_Phase_C_N_IN: J15.3 R82.1 | length 21.8
  GND/Signal 1 w0.508: R82.1@107.95,24.371 107.95,24.346 108.171,24.125 108.196,24.125 115.316,17.005 J15.3@115.316,5.588
I_Phase_C_P: C66.2 C67.2 R85.2 U6.9 | length 7.2
  GND/Signal 1 w0.381: U6.9@100.101,32.107 100.211,31.998 100.211,30.853 100.457,30.607 ; 100.465,30.599 101.473,29.591 C66.2@101.473,29.464 ; C66.2@101.645,29.636 C66.2@101.816,29.464 101.816,29.375 101.854,29.337 C67.2@101.854,27.559 ; C67.2@101.816,27.559 101.816,25.819 R85.2@101.854,25.781
I_Phase_C_P_IN: J15.2 R84.1 | length 20.2
  GND/Signal 1 w0.508: R84.1@106.172,24.346 106.393,24.125 106.393,22.766 110.236,18.923 J15.2@110.236,5.842
M0_CLKOUT_from_M0: pad.4@99.187,82.804 R16.1 U1.63 | length 8.7
  GND/Signal 1 w0.254: U1.63@93.866,77.657 94.929,77.657 98.356,81.084 R16.1@99.218,81.084 ; R16.1@99.276,81.026 R16.1@99.218,81.084 ; R16.1@99.314,81.153 99.245,81.084 R16.1@99.218,81.084 ; pad.4@99.441,82.677 99.187,82.423 99.187,81.115 R16.1@99.218,81.084
MCU_RXD: J9.2 JP8.1 pad.4@110.744,92.202 U1.55 | length 93.9
  GND/Signal 1 w0.254: U1.55@93.866,73.657 108.331,73.657 111.252,76.578 v1(111.252,82.296) 111.252,92.075 J9.2@121.539,102.362
  GND/Signal Layer 2 w0.254: JP8.1@69.342,86.36 71.374,88.392 75.692,88.392 81.788,82.296 v1(111.252,82.296)
MCU_TCK: J102.4 JP7.2 U18.35 U19.1 | length 50.3
  GND/Signal 1 w0.2: JP7.2@104.394,106.426 104.394,106.68 105.708,107.994 107.779,107.994 112.776,102.997 115.062,102.997 119.38,107.315 127.075,107.315 127.832,108.072 127.832,108.274 v1(127.889,108.331) 127.864,108.356 127.864,109.277 U19.1@127.839,109.302 ; v1(130.085,99.086) 130.134,99.086 132.435,96.784 U18.35@134.769,96.784
  GND/Signal Layer 2 w0.2: v1(127.889,108.331) 127.889,108.318 127.635,108.064 127.635,105.791 128.905,104.521 128.905,100.266 130.12,99.051 130.12,98.97 130.289,98.801 130.289,95.613 J102.4@129.559,94.884
MCU_TDI: J18.4
MCU_TDO: J18.2
MCU_TMS: J102.2 JP6.2 U18.36 U19.2 | length 37
  GND/Signal 1 w0.2: JP6.2@113.919,101.727 114.196,102.004 115.847,102.004 120.396,106.553 127.783,106.553 v1(128.44,107.209) ; U19.2@127.864,109.802 128.161,109.802 128.436,109.527 v1@128.436,107.226 ; J102.2@129.467,96.24 129.611,96.384 131.024,96.384 ; v1(131.029,97.247) 131.024,97.241 131.024,96.384 ; U18.36@134.769,96.384 131.024,96.384
  GND/Signal Layer 2 w0.2: v1(128.44,107.209) 128.44,106.764 131.024,104.18 131.024,97.253 v1(131.029,97.247)
MCU_TXD: J9.4 JP9.1 pad.3@113.792,90.551 U1.54 | length 91.2
  GND/Signal 1 w0.254: U1.54@93.866,73.157 108.839,73.157 112.268,76.586 112.268,90.297 pad.3@113.157,91.186 ; pad.3@113.792,90.551 113.792,92.075 J9.4@121.539,99.822
  GND/Signal Layer 2 w0.254: JP9.1@69.088,82.677 69.723,82.677 71.501,80.899 v1(112.268,80.899)
MSP432_SWCLK: J26.4 U18.100 | length 20.3
  GND/Signal 1 w0.2: U18.100@150.169,86.384 152.9,86.384 153.567,85.718 153.567,75.524 150.79,72.748 150.571,72.748 150.294,72.471 J26.4@150.294,70.542
MSP432_SWDIO: J26.3 U18.99 | length 21
  GND/Signal 1 w0.2: J26.3@147.754,70.577 147.754,72.205 148.724,73.175 150.04,73.175 153.005,76.14 153.005,85.729 152.75,85.984 U18.99@150.169,85.984
MSP432_TDI: J26.2 U18.98 | length 22.2
  GND/Signal 1 w0.2: J26.2@145.248,70.554 145.248,72.748 146.692,74.191 150.063,74.191 152.443,76.571 152.443,85.467 152.326,85.584 U18.98@150.169,85.584
MSP432_TDO: J26.1 U18.97 | length 23.3
  GND/Signal 1 w0.2: J26.1@142.678,70.562 142.678,73.272 144.336,74.93 149.826,74.93 151.891,76.995 151.891,85.008 151.715,85.184 U18.97@150.169,85.184
NetANT1_1: ANT1.1 C119.1 L5.2 | length 3.6
  GND/Signal 1 w0.2: L5.2@28.398,84.328 L5.2@28.529,84.328
  GND/Signal 1 w0.297: 24.892,84.328 L5.2@28.398,84.328
NetC8_1: C8.1 R6.1 U10.6 | length 3.2
  GND/Signal Layer 2 w0.15: R6.1@121.969,90.139 R6.1@122.119,89.989 ; C8.1@123.571,88.646 C8.1@123.698,88.519
  GND/Signal Layer 2 w0.19: R6.1@122.119,89.989 U10.6@122.119,88.686 123.531,88.686 C8.1@123.571,88.646
NetC11_2: C11.2 R8.1 Y1.4 | length 3.1
  GND/Signal 1 w0.254: C11.2@90.356,58.866 90.369,58.879 91.794,58.879 R8.1@91.832,58.917 ; R8.1@91.842,58.916 91.981,59.054 Y1.4@91.981,60.506
NetC17_1: C17.1 U4.14 | length 3
  GND/Signal 1 w0.381: U4.14@26.182,41.812 C17.1@26.182,44.853
NetC24_1: C24.1 U5.14 | length 3.2
  GND/Signal 1 w0.22: U5.14@62.001,41.807 62.001,44.856 C24.1@62.103,44.958
NetC35_1: C35.1 U6.14 | length 3.1
  GND/Signal 1 w0.508: U6.14@97.561,41.807 97.587,41.832 97.587,44.628 C35.1@97.79,44.831
NetC44_2: C44.2 U12.3 U12.4 U12.5 | length 8.8
  GND/Signal 1 w0.5: U12.5@139.167,117.538 139.167,119.396 139.546,119.775 140.453,119.775 ; U12.4@140.437,117.538 140.437,119.759 140.453,119.775 ; U12.3@141.707,117.538 141.664,117.538 141.664,118.805 141.342,119.127 C44.2@141.342,119.775 140.453,119.775
NetC49_1: C49.1 R110.1 R112.2 U101.2 | length 4.7
  GND/Signal 1 w0.254: R110.1@125.832,126.152 125.917,126.238 125.917,126.679 126.409,127.171 U101.2@126.409,128.133
  GND/Signal 1 w0.508: R110.1@125.832,126.152 126.999,126.152 R112.2@128.321,126.152
NetC68_1: C68.1 U7.14 | length 3.1
  GND/Signal 1 w0.508: U7.14@133.985,41.807 134.031,41.853 134.031,44.785 C68.1@133.985,44.831
NetC87_2: C87.2 R117.2 U18.96 | length 3.5
  GND/Signal 1 w0.2: U18.96@148.669,83.684 148.669,82.243 C87.2@148.85,82.062 149.928,82.062 150.177,81.813 R117.2@150.177,81.45
NetC96_1: C96.1 C97.1 C98.2 U18.87 U18.115 | length 18.6
  GND/Signal 1 w0.15: v1@149.098,92.329 149.153,92.384 v1(149.187,92.384) U18.115@150.169,92.384
  GND/Signal 1 w0.254: U18.87@145.054,83.669 v1(145.054,84.651)
  GND/Signal Layer 2 w0.254: C96.1@145.054,85.238 C96.1@145.108,85.292 ; C98.2@148.682,92.485 C98.2@148.783,92.384
  GND/Signal Layer 2 w0.3: v1(145.054,84.651) C96.1@145.054,85.238 ; C98.2@148.719,92.485 C97.1@148.719,93.907 ; C98.2@148.783,92.384 v1(149.187,92.384)
  GND/Signal Layer 2 w0.5: C96.1@145.108,85.292 149.263,85.292 150.089,86.118 150.089,92.906 149.087,93.908 C97.1@148.718,93.908
NetC99_2: C99.2 R128.1 U18.68 | length 5.7
  GND/Signal 1 w0.2: R128.1@134.391,81.39 134.491,81.39 135.523,82.423 v1(137.16,82.423) 137.469,82.732 U18.68@137.469,83.684
  GND/Signal Layer 2 w0.3: v1(137.16,82.423) 137.16,82.477 137.382,82.699 C99.2@137.382,83.4
NetC104_2: C104.2 U14.16 | length 3.1
  GND/Signal 1 w0.24: C104.2@50.146,91.818 50.146,91.082 50.55,90.678 U14.16@50.55,88.895 ; C104.2@50.149,91.821 C104.2@50.165,91.821
NetC113_1: C113.1 J21.1 | length 5.5
  GND/Signal 1 w0.2: C113.1@35.814,85.344 J21.1@35.814,90.805
NetC113_2: C113.2 C115.1 C117.2 D6.2 L4.2 | length 10.8
  GND/Signal 1 w0.297: C117.2@35.806,84.328 L4.2@46.588,84.328 L4.2@46.609,84.328
NetC117_1: C117.1 C118.1 L5.1 | length 5.7
  GND/Signal 1 w0.297: L5.1@29.006,84.328 C117.1@34.671,84.328
NetC122_1: C122.1 U18.89 Y2.3 | length 3.9
  GND/Signal 1 w0.2: U18.89@145.869,83.684 145.869,80.486 Y2.3@146.363,79.992
NetC123_1: C123.1 U18.88 Y2.1 | length 6.3
  GND/Signal 1 w0.2: Y2.1@144.163,78.392 144.216,78.392 145.21,79.386 145.21,80.928 144.757,81.381 C123.1@144.685,81.381 145.469,82.165 U18.88@145.469,83.684
NetD1_2: D1.2 R1.1 | length 1.5
  GND/Signal 1 w0.254: D1.2@101.6,64.196 101.854,64.45 R1.1@101.854,65.6
NetD2_2: D2.2 R2.1 | length 1.9
  GND/Signal 1 w0.254: R2.1@98.517,60.96 98.517,59.09 D2.2@98.552,59.055
NetL3_2: L3.2 U14.17 | length 3.5
  GND/Signal 1 w0.2: L3.2@48.768,91.821 49.126,91.463 49.126,91.209 50.05,90.285 U14.17@50.05,88.895
NetLED0_2: LED0.2 R111.1 | length 1.4
  GND/Signal 1 w0.3: LED0.2@129.388,117.433 R111.1@129.388,118.821
NetLED1_2: LED1.2 R109.1 | length 2.9
  GND/Signal 1 w0.4: LED1.2@116.078,82.389 116.112,82.423 117.602,82.423 118.137,82.958 118.137,83.401 118.175,83.439 R109.1@118.237,83.439
NetLED2_1: LED2.1 R119.1 | length 1.4
  GND/Signal 1 w0.2: R119.1@147.971,101.93 LED2.1@149.42,101.93
NetLED3_1: LED3.1 R120.1 | length 1.4
  GND/Signal 1 w0.2: R120.1@147.971,104.089 LED3.1@149.42,104.089
NetLED6_2: LED6.2 R108.1 | length 1.8
  GND/Signal 1 w0.3: R108.1@121.356,124.898 LED6.2@121.356,126.674
NetLED7_2: LED7.2 R49.1 | length 1.9
  GND/Signal 1 w0.762: LED7.2@139.075,127.283 139.333,127.541 R49.1@140.903,127.541
NetR5_1: R5.1 U10.1 | length 1.9
  GND/Signal 1 w0.16: R5.1@121.514,85.034 121.569,85.09 v1(122.428,85.09)
  GND/Signal Layer 2 w0.2: U10.1@122.119,85.936 122.319,85.736 122.319,85.281 122.428,85.171 v1(122.428,85.09)
NetR11_1: R11.1 Y1.1 | length 1.8
  GND/Signal 1 w0.2: Y1.1@91.981,62.106 91.981,63.743 R11.1@92.058,63.82
  GND/Signal 1 w0.254: R11.1@92.043,63.805 R11.1@92.049,63.811
NetR14_2: R14.2 U2.1 | length 2.8
  GND/Signal 1 w0.254: U2.1@66.331,67.242 66.331,69.016 66.657,69.342 66.657,69.832 R14.2@66.675,69.85
NetR27_1: R27.1 U4.11 | length 6.5
  GND/Signal 1 w0.381: U4.11@29.972,41.91 29.972,42.542 32.258,44.828 R27.1@32.258,47.46
NetR29_1: R29.1 U4.20 | length 5
  GND/Signal 1 w0.381: R29.1@14.732,44.45 16.674,44.45 18.542,42.582 U4.20@18.542,42.164
NetR30_1: R30.1 U4.12 | length 6.5
  GND/Signal 1 w0.381: U4.12@28.702,41.656 28.702,43.18 30.48,44.958 R30.1@30.48,47.435
NetR34_1: R34.1 U5.11 | length 6.2
  GND/Signal 1 w0.406: U5.11@65.811,41.807 65.908,41.904 65.908,43.048 67.945,45.085 R34.1@67.945,47.117
NetR37_1: R37.1 U5.20 | length 6
  GND/Signal 1 w0.508: R37.1@49.822,44.323 52.578,44.323 54.298,42.603 54.335,42.603 54.381,42.557 U5.20@54.381,41.807
NetR38_1: R38.1 U5.12 | length 6.2
  GND/Signal 1 w0.406: U5.12@64.541,41.807 64.541,43.459 65.913,44.831 65.913,47.244 R38.1@66.04,47.371
NetR43_1: R43.1 U6.11 | length 6.4
  GND/Signal 1 w0.406: U6.11@101.371,41.807 101.42,41.856 101.42,43.127 103.378,45.085 R43.1@103.378,47.371
NetR45_1: R45.1 U6.20 | length 5.6
  GND/Signal 1 w0.406: R45.1@85.979,44.069 85.979,44.115 86.187,44.323 88.138,44.323 89.807,42.654 89.845,42.654 89.941,42.557 U6.20@89.941,41.807
NetR46_1: R46.1 U6.12 | length 6.1
  GND/Signal 1 w0.406: U6.12@100.101,41.807 100.101,43.332 101.6,44.831 R46.1@101.6,47.244
NetR50_2: R50.2 U12.6 | length 1.9
  GND/Signal 1 w0.2: R50.2@137.877,119.454 137.897,119.434 U12.6@137.897,117.538
NetR51_1: R51.1 U12.11 | length 2.4
  GND/Signal 1 w0.27: U12.11@137.897,107.788 137.897,107.283 137.487,106.874 137.487,106.241 R51.1@137.944,105.784
NetR52_2: R52.2 U12.7 | length 1.9
  GND/Signal 1 w0.2: U12.7@136.627,117.538 136.627,119.381 R52.2@136.7,119.454
NetR53_1: R53.1 U12.10 | length 2.4
  GND/Signal 1 w0.27: R53.1@136.611,105.766 137.067,106.223 137.067,106.735 136.699,107.103 U12.10@136.699,107.833
NetR56_1: R56.1 R57.2 R60.1 R123.1 | length 7.3
  GND/Signal 1 w0.381: R60.1@22.606,19.177 22.992,19.784 23.323,20.116 24.126,20.919 24.29,20.961 R57.2@24.55,21.082 ; R57.2@24.525,21.107 24.511,21.121 24.511,22.383 24.734,22.606 25.692,22.606 R56.1@25.908,22.822 ; R57.2@24.684,21.036 24.684,20.11 24.886,19.908 24.886,19.783 25.021,19.648 R123.1@25.146,19.648
NetR57_1: R57.1 R61.1 R100.2 U15.5 | length 14.5
  GND/Signal 1 w0.381: U15.5@23.484,13.843 23.515,13.874 25.558,13.874 27.559,15.875 27.559,20.917 27.768,21.127 26.295,21.127 R57.1@26.25,21.082 ; R61.1@27.813,21.209 28.791,21.209 29.371,20.63 29.371,20.605 29.655,20.32 R100.2@30.099,20.32
NetR58_1: R58.1 R59.2 | length 3.6
  GND/Signal 1 w1.27: R58.1@15.367,19.558 15.335,19.526 15.335,18.034 16.584,16.785 R59.2@16.584,16.51
NetR59_1: R59.1 R60.2 | length 2.9
  GND/Signal 1 w0.762: R59.1@19.484,16.51 19.558,16.584 19.558,19.177 R60.2@19.685,19.304
NetR62_1: R62.1 R63.2 R66.1 R125.1 | length 7.3
  GND/Signal 1 w0.4: R66.1@58.406,20.537 58.419,20.55 60.301,20.55 60.452,20.701 R63.2@60.491,20.701 60.541,20.701 60.741,20.501 60.741,20.169 61.849,19.061 R125.1@61.849,19.011
  GND/Signal 1 w0.5: R63.2@60.491,20.701 60.491,21.82 61.497,22.826 61.815,22.826 R62.1@61.849,22.86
